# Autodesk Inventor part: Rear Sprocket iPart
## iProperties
Shininess: 64.0
Length Units: 11269
Angle Units: 11279
Time Units: 11290
Mass Units: 11283
Length Display Precision: 3
Angle Display Precision: 2
Compacted: True
Part Number: Rear Sprocket iPart
Document SubType Name: Modeling
Created: 2004-03
Designer: rak
Manufacturer: Standard
Standards Organization: Custom
Description: Rear Sprocket iPart
Density: 0.0
Volumn: 0.0
Area: 0.0
PropertySet Name: Model Information
Control State: 0
Master: False
Checked Out: False
HolePatternCount: 6.000 ul
Author: rak
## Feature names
1. Extrusion1
2. Extrusion2
3. Circular Pattern1
4. Extrusion3
5. Chamfer1
6. Circular Pattern2
7. Hole1
8. Chamfer2
9. Circular Pattern3
10. Revolution1
